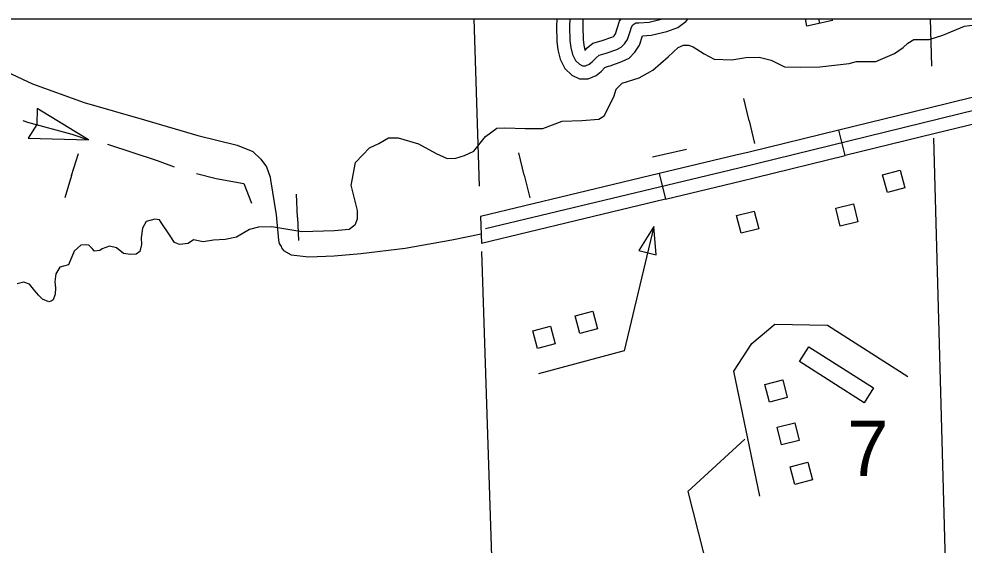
# Model space of a CAD drawing. Extents: x 155 to 3386, y 68 to 2138.
# Drawn here: x 1855.9 to 2010, y 1223.3 to 1309 of the extents above; entities that cross this region are included whole.
import ezdxf

# ---------------------------------------------------------------- set-up
doc = ezdxf.new("R2010")
doc.units = 0
for name, color, linetype in [('Default', 7, 'Continuous'), ('E_No Plot', 7, 'Continuous'), ('Level 31', 7, 'Continuous'), ('Level 32', 7, 'Continuous'), ('Level 33', 7, 'Continuous'), ('Level 35', 7, 'Continuous'), ('Level 40', 7, 'Continuous'), ('Level 43', 7, 'Continuous'), ('Level 45', 7, 'Continuous'), ('Level 5', 7, 'Continuous'), ('Level 56', 7, 'Continuous'), ('Level 57', 7, 'Continuous'), ('Level 58', 7, 'Continuous'), ('Level 6', 7, 'Continuous')]:
    doc.layers.add(name, color=color, linetype=linetype)

msp = doc.modelspace()

# ---------------------------------------------------------------- linework, layer by layer
at = {"layer": 'Default'}
msp.add_lwpolyline([(1150.5, 1308.99), (2342.15, 1308.99), (2342.15, 348.58), (1150.5, 348.58)], close=True, dxfattribs=at)
at = {"layer": 'E_No Plot'}
msp.add_lwpolyline([(1150.5, 1308.99), (2342.15, 1308.99), (2342.15, 348.58), (1150.5, 348.58)], close=True, dxfattribs=at)
msp.add_lwpolyline([(1150.5, 1308.99), (2342.15, 1308.99), (2342.15, 348.58), (1150.5, 348.58)], close=True, dxfattribs=at)
at = {"layer": 'Level 31'}
for p, q in [((1990.62, 1286.72), (1989.6, 1290.89)), ((1960.29, 1283.78), (1961.29, 1279.61))]:
    msp.add_line(p, q, dxfattribs=at)
for points in [[(2067.76, 1308.99), (2064.86, 1307.84), (2060.55, 1306.21), (2056.44, 1304.93), (2047.48, 1302.62), (2015.13, 1294.92), (1973.29, 1284.69), (1931.94, 1274.77)], [(2018.93, 1298.03), (2014.63, 1297), (2004.26, 1294.47)], [(2004.26, 1294.47), (1989.6, 1290.89)], [(2019.92, 1293.86), (2015.63, 1292.84), (2005.27, 1290.3)], [(1989.6, 1290.89), (1974.95, 1287.3)], [(2005.27, 1290.3), (1990.62, 1286.72)], [(1974.95, 1287.3), (1972.78, 1286.78), (1960.29, 1283.78)], [(1975.97, 1283.14), (1990.62, 1286.72)], [(1960.29, 1283.78), (1945.62, 1280.26)], [(1961.29, 1279.61), (1973.79, 1282.61), (1975.97, 1283.14)], [(1945.62, 1280.26), (1931.16, 1276.79), (1931.3, 1272.42)], [(1961.29, 1279.61), (1946.62, 1276.09)], [(1946.62, 1276.09), (1931.3, 1272.42)]]:
    msp.add_lwpolyline(points, dxfattribs=at)
at = {"layer": 'Level 32'}
msp.add_line((1988.57, 1308.71), (1984.38, 1307.81), dxfattribs=at)
for points in [[(1984.38, 1307.81), (1984.12, 1308.99)], [(1986.47, 1308.26), (1986.32, 1308.99)], [(1988.57, 1308.71), (1988.51, 1308.99)]]:
    msp.add_lwpolyline(points, dxfattribs=at)
at = {"layer": 'Level 33'}
for points in [[(1835.49, 1308.99), (1836.53, 1308.49), (1851.31, 1301.59), (1858.12, 1298.41), (1866.53, 1295.37), (1876.36, 1292.56), (1885.03, 1290.02), (1891.48, 1288.41), (1894, 1287.38), (1895.33, 1286.16), (1896.25, 1284.9), (1896.84, 1283.22), (1896.9, 1282.78), (1897.81, 1277.07)], [(1897.81, 1277.07), (1898.2, 1272.92), (1898.31, 1272.42), (1898.62, 1271.88), (1898.69, 1271.67), (1899.01, 1271.27), (1900.3, 1270.56), (1903.13, 1270.24), (1907.28, 1270.37), (1911.65, 1270.78), (1918.84, 1271.61), (1926.46, 1273), (1931.25, 1273.95)]]:
    msp.add_lwpolyline(points, dxfattribs=at)
at = {"layer": 'Level 35'}
for points in [[(1991.28, 1301.73), (1992.44, 1302.06), (1995.62, 1302.06), (1998.68, 1303.37), (2000.06, 1304.31), (2000.81, 1305.06), (2001.8, 1305.62), (2002.99, 1305.62), (2004.3, 1305.62), (2006.55, 1306.37), (2010.05, 1307.81), (2011.68, 1308.03), (2015.42, 1308.16), (2017.98, 1308.53), (2019.17, 1308.84), (2019.49, 1308.99)], [(1951.32, 1293.22), (1952.89, 1296.27), (1953.27, 1297.52), (1954.27, 1298.52), (1957.01, 1299.39), (1959.26, 1300.64), (1961.76, 1302.83), (1963.38, 1304.33), (1964.26, 1304.7), (1965.07, 1304.7), (1965.82, 1304.45), (1967.63, 1303.33), (1969.25, 1302.45), (1972.12, 1302.33), (1974.39, 1302.7), (1976.58, 1302.77), (1978.52, 1302.27), (1980.7, 1301.21), (1983.32, 1301.14), (1986.51, 1301.19), (1991.28, 1301.73)], [(1910.04, 1281.85), (1910.79, 1285.61), (1913.05, 1287.97), (1914.56, 1288.69), (1916.12, 1289.63), (1917.75, 1289.63), (1921.05, 1288.63), (1923.93, 1287.07), (1925.74, 1286.26), (1927.11, 1286.32), (1928.55, 1286.76), (1930.04, 1287.44), (1931.98, 1289.82), (1933.79, 1291.19), (1935.1, 1291.25), (1938.41, 1291.13), (1941.34, 1291.13), (1944.47, 1292.31), (1947.65, 1292.44), (1950.46, 1292.63), (1951.32, 1293.22)], [(1910.03, 1281.88), (1911.02, 1277.77), (1911.02, 1276.38), (1910.64, 1275.36), (1909.75, 1274.66), (1907.34, 1274.47), (1902.01, 1274.28), (1897.12, 1275.11), (1894.96, 1275.04), (1893.5, 1274.66), (1891.34, 1273.45), (1889.5, 1273.07), (1887.6, 1272.95), (1885.94, 1272.69), (1884.36, 1273.01), (1883.48, 1272.39), (1882.09, 1272.23), (1881.23, 1272.58), (1880.44, 1273.82), (1879.1, 1275.82), (1878.79, 1276.27), (1878.02, 1276.36), (1876.63, 1275.98), (1876.02, 1274.9), (1875.8, 1273.31), (1875.87, 1272.23), (1875.61, 1271.09), (1874.98, 1270.68), (1874.06, 1270.61), (1872.91, 1270.74), (1871.77, 1271.69), (1870.63, 1271.95), (1869.45, 1271.53), (1869.1, 1271.28), (1868.21, 1271.15), (1867.83, 1271.56), (1867.29, 1272.1), (1866.69, 1272.17), (1865.96, 1272.14), (1864.88, 1271.12), (1863.96, 1268.93), (1863.17, 1268.71), (1862.56, 1268.52), (1861.9, 1267.47), (1861.74, 1266.17), (1861.83, 1265.15), (1861.8, 1264.13), (1861.45, 1263.24), (1861.14, 1263.02), (1860.75, 1262.89), (1859.74, 1263.34), (1859.07, 1263.97), (1858.28, 1264.96), (1857.61, 1265.75), (1856.66, 1266.1), (1855.61, 1265.85)]]:
    msp.add_lwpolyline(points, dxfattribs=at)
at = {"layer": 'Level 40'}
for p, q in [((1974.95, 1292.36), (1974.07, 1296.02)), ((1974.95, 1292.36), (1975.83, 1288.69)), ((1864.47, 1283.45), (1865.57, 1287.06)), ((1938.29, 1283.51), (1937.4, 1287.18)), ((1864.47, 1283.45), (1863.38, 1279.84)), ((1938.29, 1283.51), (1939.18, 1279.84)), ((1901.31, 1276.65), (1901.16, 1280.42)), ((1901.31, 1276.65), (1901.46, 1272.88))]:
    msp.add_line(p, q, dxfattribs=at)
at = {"layer": 'Level 43'}
for p, q in [((1858.86, 1294.42), (1858.79, 1291.81)), ((1867.22, 1289.29), (1858.86, 1294.42)), ((1858.78, 1291.77), (1857.41, 1289.55)), ((1857.41, 1289.55), (1867.22, 1289.29))]:
    msp.add_line(p, q, dxfattribs=at)
for points in [[(1856.53, 1292.45), (1857.3, 1292.17), (1864.51, 1290.19), (1867.22, 1289.29)], [(1870.34, 1288.57), (1878.42, 1285.91), (1881.22, 1284.88)], [(1884.82, 1283.78), (1888.05, 1282.99), (1892.55, 1282.16), (1893.78, 1278.98)]]:
    msp.add_lwpolyline(points, dxfattribs=at)
at = {"layer": 'Level 45'}
for points in [[(1943.57, 1308.99), (1943.53, 1307.78), (1943.59, 1305.31), (1943.77, 1303.96), (1944.12, 1302.44), (1944.91, 1300.89), (1946.05, 1299.81), (1947.31, 1299.22), (1948.73, 1299.22), (1950.01, 1299.76), (1950.8, 1300.45), (1951.43, 1301.08), (1951.52, 1301.15), (1952.03, 1301.3)], [(1945.72, 1308.99), (1945.67, 1307.77), (1945.73, 1305.47), (1945.88, 1304.34), (1946.15, 1303.18), (1946.65, 1302.19), (1947.28, 1301.6), (1947.79, 1301.36), (1948.29, 1301.36), (1948.86, 1301.6), (1949.34, 1302.02), (1949.99, 1302.67), (1950.5, 1303.09), (1951.63, 1303.42), (1953.39, 1304.01), (1954.1, 1304.37), (1954.64, 1304.91), (1955.12, 1305.65), (1955.54, 1306.94), (1955.77, 1307.65), (1956.01, 1308.01), (1956.29, 1308.25), (1956.5, 1308.34), (1956.98, 1308.37), (1958.65, 1308.49), (1960.81, 1308.99)], [(1947.86, 1308.99), (1947.81, 1307.76), (1947.87, 1305.64), (1947.99, 1304.72), (1948.17, 1303.92), (1948.19, 1303.9), (1948.55, 1304.26), (1949.48, 1305.02), (1950.83, 1305.42)], [(1950.83, 1305.42), (1950.99, 1305.46), (1952.56, 1306), (1952.83, 1306.13), (1952.96, 1306.26), (1953.16, 1306.58), (1953.5, 1307.61), (1953.83, 1308.6), (1954.09, 1308.99)], [(1952.03, 1301.3), (1952.27, 1301.37), (1954.22, 1302.03), (1955.37, 1302.61), (1956.32, 1303.56), (1957.07, 1304.73), (1957.57, 1306.26), (1958.97, 1306.36), (1961.54, 1306.96), (1963.34, 1307.59), (1964.65, 1308.58), (1965, 1308.99)]]:
    msp.add_lwpolyline(points, dxfattribs=at)
at = {"layer": 'Level 5'}
for points in [[(2004.47, 1308.99), (2004.68, 1301.28)], [(2005, 1289.56), (2007.28, 1206.73)]]:
    msp.add_lwpolyline(points, dxfattribs=at)
at = {"layer": 'Level 56'}
for points in [[(1959.22, 1286.51), (1964.72, 1287.75)], [(1959.4, 1275.14), (1954.6, 1254.9), (1940.58, 1251.17)], [(1974.27, 1240.53), (1964.98, 1231.96), (1974.99, 1192.46)]]:
    msp.add_lwpolyline(points, dxfattribs=at)
for points in [[(1996.7, 1283.56), (1999.56, 1284.36), (2000.36, 1281.48), (1997.5, 1280.69)], [(1989.78, 1275.24), (1989.08, 1278.13), (1991.98, 1278.84), (1992.68, 1275.95)], [(1973.63, 1274.07), (1972.9, 1276.95), (1975.79, 1277.69), (1976.52, 1274.8)], [(1956.97, 1271.23), (1959.81, 1270.55), (1959.4, 1275.14)], [(1949.47, 1261.39), (1950.23, 1258.51), (1947.35, 1257.75), (1946.59, 1260.62)], [(1942.55, 1258.9), (1943.31, 1256.03), (1940.43, 1255.26), (1939.66, 1258.14)], [(1995.23, 1248.85), (1993.7, 1246.44), (1983.16, 1253.17), (1984.7, 1255.58)], [(1978.28, 1246.54), (1977.54, 1249.43), (1980.43, 1250.16), (1981.17, 1247.28)], [(1980.24, 1239.57), (1979.51, 1242.46), (1982.4, 1243.19), (1983.13, 1240.31)], [(1982.38, 1233.14), (1981.65, 1236.02), (1984.54, 1236.76), (1985.28, 1233.87)]]:
    msp.add_lwpolyline(points, close=True, dxfattribs=at)
at = {"layer": 'Level 58'}
msp.add_lwpolyline([(1976.69, 1231.23), (1972.47, 1251.61), (1975.41, 1256.12), (1979.15, 1259.27), (1987.75, 1259.08), (2000.82, 1250.73)], dxfattribs=at)
at = {"layer": 'Level 6'}
for points in [[(1930.99, 1281.74), (1930.09, 1308.99)], [(1807.32, 1046.44), (1862.06, 1047.97), (1857.33, 1202.89), (1933.53, 1204.84), (1931.34, 1271.07)]]:
    msp.add_lwpolyline(points, dxfattribs=at)

# ---------------------------------------------------------------- texts
at = {"layer": 'Level 57'}
msp.add_text('7', height=9.05, dxfattribs=at).set_placement((1990.92, 1234.49))

doc.saveas('drawing.dxf')
